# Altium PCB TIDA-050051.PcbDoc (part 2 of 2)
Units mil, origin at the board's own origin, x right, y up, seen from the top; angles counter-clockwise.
Board outline 1055.12 x 796.27 mil, 6 copper layers (Top Layer, Signal Layer 1, Signal Layer 2, Signal Layer 3, Signal Layer 4, Bottom Layer), stack 61 mil thick; 108 components, 65 nets, 370 pads, 157 vias.
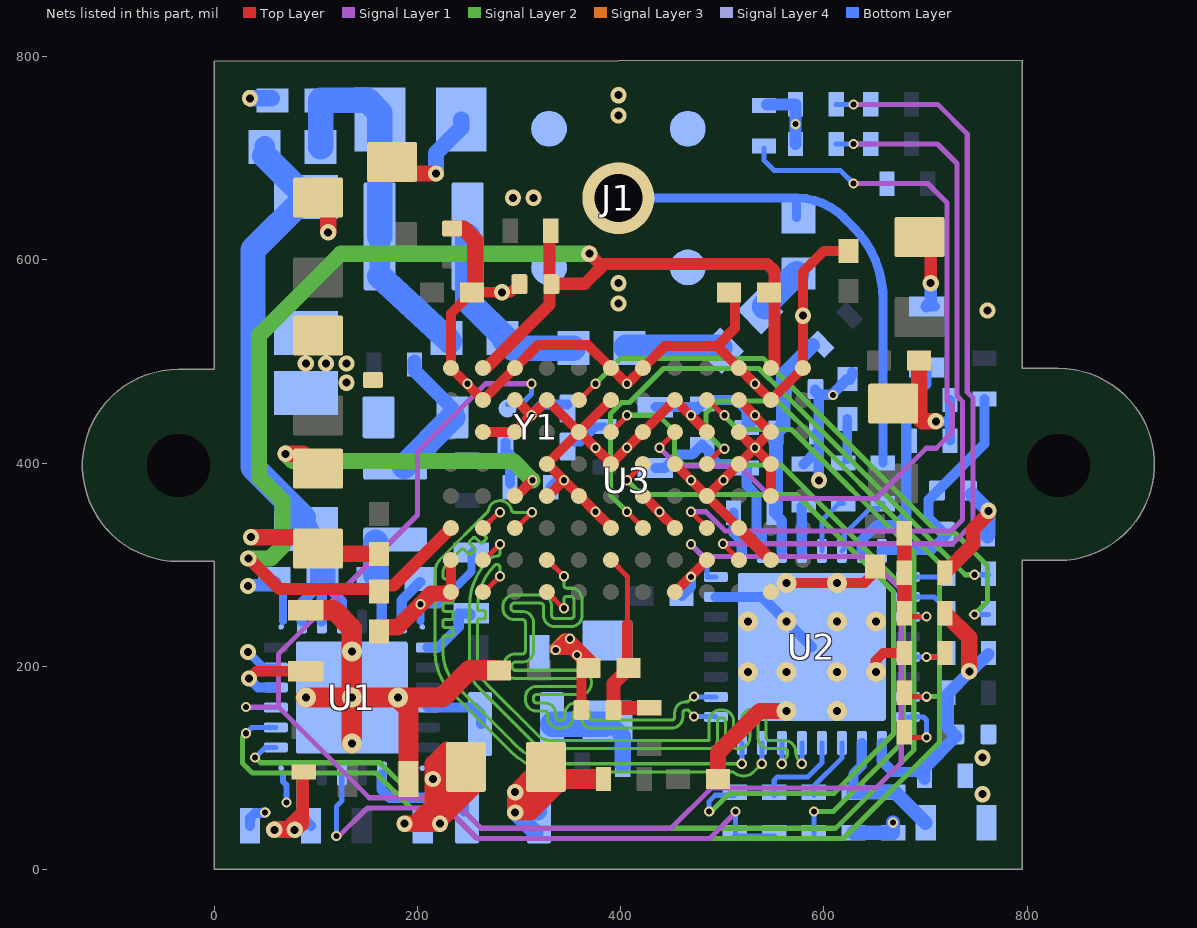
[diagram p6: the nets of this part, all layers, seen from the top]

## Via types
v1: diameter 10, hole 6, Top Layer to Bottom Layer, tented both sides, 79 vias
v2: diameter 16, hole 7.87, Top Layer to Bottom Layer, tented both sides, 61 vias
v3: diameter 19.68, hole 7.87, Top Layer to Bottom Layer, 17 vias

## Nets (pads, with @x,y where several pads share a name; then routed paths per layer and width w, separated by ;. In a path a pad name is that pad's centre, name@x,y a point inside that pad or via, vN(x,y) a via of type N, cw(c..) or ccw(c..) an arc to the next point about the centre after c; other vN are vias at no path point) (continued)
CSI0_D1_N: U2.2 U3.B9 | length 643.2
  Top Layer w3: U3.B9@327.31,304.52 U3.B9@327.97,304.52
  Top Layer w5: U3.B9@327.97,304.52 v1(343.99,288.5)
  Signal Layer 2 w3: 310.75,207.2 cw(c303.04,214.91) 303.04,204 296,204 ccw(c296,201) 293.88,203.12 ccw(c296,201) 293,201 293,199 ccw(c296,199) 293.88,196.88 ccw(c296,199) 296,196 360,196 cw(c360,185.08) 367.72,192.8 367.77,192.76 cw(c360.05,185.03) 370.97,185.03 370.97,183 cw(c359.97,183) 367.75,175.22 ; 310.78,207.22 ccw(c303,215) 314,215 314,243.03 ccw(c303.08,243.03) 310.8,250.76 310.76,250.8 ccw(c303.03,243.08) 303.03,254 295,254 cw(c295,257) 292.88,254.88 cw(c295,257) 292,257 292,259 cw(c295,259) 292.88,261.12 cw(c295,259) 295,262 321,262 cw(c321,259) 323.12,261.12 cw(c321,259) 324,259 324,249.99 ccw(c334.98,249.99) 327.21,242.23 ; 327.22,242.22 ccw(c335,250) 335,239 351.04,239 ccw(c351.04,249.91) 358.75,242.2 ; v1(343.99,288.5) 344,279.75 ccw(c347,279.75) 344.88,277.63 ccw(c347,279.75) 347,276.75 352.28,276.75 cw(c352.28,268.85) 357.87,274.43 357.93,274.38 cw(c348.1,264.55) 362,264.55 362,250 cw(c351,250) 358.78,242.22 ; 348.22,160.78 ccw(c356,153) 345,153 345,150 cw(c342,150) 344.12,147.88 cw(c342,150) 342,147 339,147 cw(c339,150) 336.88,147.88 cw(c339,150) 336,150 336,153.03 ccw(c325.08,153.03) 332.8,160.76 332.76,160.8 ccw(c325.03,153.08) 325.03,164 317,164 cw(c317,167) 314.88,164.88 cw(c317,167) 314,167 314,169 cw(c317,169) 314.88,171.12 cw(c317,169) 317,172 360,172 ccw(c360.01,182.91) 367.72,175.2 ; 348.25,160.8 cw(c355.96,153.09) 355.96,164 358.03,164 cw(c358.03,153.08) 365.76,160.8 365.8,160.76 cw(c358.08,153.03) 369,153.03 369,150 ccw(c372,150) 369.88,147.88 ccw(c372,150) 372,147 450,147 ccw(c450,150) 452.12,147.88 ccw(c450,150) 453,150 453,154 cw(c464,154) 456.22,161.78 ; 456.25,161.8 cw(c463.96,154.09) 463.96,165 466,165 470.74,169.74 cw(c472,168.47) v1(472,170.26)
  Bottom Layer w5: v1(472,170.26) 472.47,169.79 U2.2@493.51,169.79
CSI0_D1_P: U2.1 U3.A9 | length 644.1
  Top Layer w3: v1@343.33,257 v1(343.99,257)
  Top Layer w5: U3.A9@327.31,273.03 v1@343.33,257
  Signal Layer 2 w3: 287.22,249.22 ccw(c295,257) 295,246 303,246 cw(c303,243) 305.12,245.12 cw(c303,243) 306,243 306,215 cw(c303,215) 305.12,212.88 cw(c303,215) 303,212 295.98,212 ccw(c295.98,201.06) 288.24,208.79 288.2,208.75 ccw(c295.92,201.04) 285,201.04 285,198.97 ccw(c295.92,198.97) 288.2,191.24 ; 287.2,249.24 cw(c294.92,256.97) 284,256.97 284,259.04 cw(c294.92,259.04) 287.2,266.75 287.24,266.79 cw(c294.98,259.06) 294.98,270 321.03,270 cw(c321.03,259.08) 328.76,266.8 328.8,266.76 cw(c321.08,259.03) 332,259.03 332,250 ccw(c335,250) 332.88,247.88 ccw(c335,250) 335,247 351,247 ccw(c351,250) 353.12,247.88 ccw(c351,250) 354,250 354,264.51 ccw(c348,264.51) 352.24,268.75 347,268.75 ccw(c347,265.75) 344.88,267.87 ccw(c347,265.75) 344,265.75 v1(343.99,257) ; 288.22,191.22 ccw(c296,199) 296,188 360,188 ; 309.22,159.22 ccw(c317,167) 317,156 325,156 cw(c325,153) 327.12,155.12 cw(c325,153) 328,153 328,149.97 ccw(c338.92,149.97) 331.2,142.24 ; 309.2,159.24 cw(c316.92,166.97) 306,166.97 306,169.04 cw(c316.92,169.04) 309.2,176.75 309.24,176.79 cw(c316.98,169.06) 316.98,180 360,180 ; 331.22,142.22 ccw(c339,150) 339,139 342.02,139 ccw(c342.02,149.94) 349.76,142.2 ; 349.78,142.22 ccw(c342,150) 353,150 353,153 cw(c356,153) 353.88,155.12 cw(c356,153) 356,156 358,156 cw(c358,153) 360.12,155.12 cw(c358,153) 361,153 361,149.97 ccw(c371.92,149.97) 364.2,142.24 ; 359.97,180 ccw(c359.97,183) 362.09,180.88 ccw(c359.97,183) 362.97,183 362.97,185 ccw(c359.97,185) 362.09,187.12 ccw(c359.97,185) 359.97,188 ; 364.22,142.22 ccw(c372,150) 372,139 450.02,139 ccw(c450.02,149.94) 457.76,142.2 ; 457.78,142.22 ccw(c450,150) 461,150 461,154 cw(c464,154) 461.88,156.12 cw(c464,154) 464,157 466,157 472,151 v1(472,150.57)
  Bottom Layer w5: v1(472,150.57) 493.04,150.57 U2.1@493.51,150.1
CSI0_D2_N: U2.32 U3.C11 | length 650.6
  Top Layer w5: U3.C11@264.31,336.02 279.79,351.5 v1(281,351.5)
  Signal Layer 2 w3: v1(281,351.5) 279.74,351.5 264.24,336 262.83,334.59 ccw(c264.24,333.17) 262.83,331.76 267.07,327.51 cw(c265.66,326.1) 267.07,324.69 264.24,321.86 cw(c262.83,323.27) 261.41,321.86 257.17,326.1 ccw(c255.76,324.69) 254.34,326.1 251.51,323.27 ccw(c252.93,321.86) 251.51,320.44 255.76,316.2 cw(c254.34,314.79) 255.76,313.37 252.93,310.54 cw(c251.51,311.96) 250.1,310.54 245.86,314.79 ccw(c244.44,313.37) 243.03,314.79 238.79,310.54 236.12,307.88 228.71,300.47 ccw(c237.72,291.49) 225,291.49 225,288 ccw(c227,288) 227,286 233,286 cw(c233,284) 235,284 235,280 cw(c233,280) 233,278 227,278 ccw(c227,276) 225,276 225,272 ccw(c227,272) 227,270 233,270 cw(c233,268) 235,268 235,264 cw(c233,264) 233,262 227,262 ccw(c227,260) 225,260 225,256 ccw(c227,256) 227,254 233,254 cw(c233,252) 235,252 235,248 cw(c233,248) 233,246 227,246 ccw(c227,244) 225,244 225,240 ccw(c227,240) 227,238 233,238 cw(c233,236) 235,236 235,232 cw(c233,232) 233,230 227,230 ccw(c227,228) 225,228 225,222 225,218 225,214 ccw(c273.28,214) 239.14,179.86 288.47,130.53 297.66,121.34 ccw(c339.53,163.21) 339.53,104 v1(519,104)
  Bottom Layer w5: v1(519,104) 519.1,104.1 U2.32@519.1,124.51
CSI0_D2_P: U2.31 U3.C10 | length 641.4
  Top Layer w3: U3.C10@295.81,336.02 U3.C10@297.02,336.02
  Top Layer w5: U3.C10@297.02,336.02 v1(312.5,351.5)
  Signal Layer 2 w3: 268.85,351.92 268.42,351.5 223.01,306.08 ccw(c237.52,291.57) 217,291.57 217,213.93 ccw(c273.12,213.93) 233.44,174.25 249.04,158.65 282.82,124.87 292,115.69 ; 268.87,351.94 ccw(c266.72,354.04) 269.68,353.51 cw(c281,351.5) 292.25,353.88 ccw(c295.19,354.5) 295.19,351.5 v1(312.5,351.5) ; 292.03,115.66 ccw(c339.49,163.11) 339.49,96 509.53,96 cw(c509.55,93) 511.51,95.28 ccw(c520.73,106.01) 530.04,95.36 v1(538.68,104)
  Bottom Layer w5: v1(538.68,104) 538.79,104.1 U2.31@538.79,124.51
CSI0_D3_N: U2.30 U3.B11 | length 641.2
  Top Layer w3: U3.B11@264.31,304.52 U3.B11@265.52,304.52
  Top Layer w5: U3.B11@265.52,304.52 v1(281,320)
  Signal Layer 2 w3: 260.12,178.91 cw(c282.15,200.93) 251,200.86 cw(c282.15,200.93) 251,200.93 251,258.67 cw(c316.53,258.67) 270.19,305 270.25,305.06 cw(c277.96,297.35) 277.96,308.25 ; 260.6,178.43 312.81,126.22 ccw(c330.24,143.64) 330.17,119 ccw(c330.24,143.64) 330.24,119 487,119 ccw(c487,127) 492.66,121.34 ; 278,308.25 ccw(c278,311.25) 280.12,309.13 ccw(c278,311.25) 281,311.25 v1(281,320) ; 492.68,121.37 ccw(c487.08,126.96) 495,126.96 495,146 cw(c498,146) 495.88,148.12 cw(c498,146) 498,149 500,149 cw(c500,146) 502.12,148.12 cw(c500,146) 503,146 503,129.97 ccw(c513.92,129.97) 506.2,122.24 ; 506.22,122.22 ccw(c514,130) 514,119 516.02,119 ccw(c516.02,129.94) 523.76,122.2 ; 523.78,122.22 ccw(c516,130) 527,130 527,147 cw(c530,147) 527.88,149.12 cw(c530,147) 530,150 532,150 cw(c532,147) 534.12,149.12 cw(c532,147) 535,147 535,129.97 ccw(c545.92,129.97) 538.2,122.24 ; 538.22,122.22 ccw(c546,130) 546,119 561,119 cw(c561.02,116.06) 563.1,118.14 cw(c561.06,116.02) 564,116.02 564,112.91 cw(c547.08,117.5) 559.46,105.09 v1(558.37,104)
  Bottom Layer w5: v1(558.37,104) 558.47,104.1 U2.30@558.47,124.51
CSI0_D3_P: U2.29 U3.A11 | length 641.6
  Top Layer w3: U3.A11@264.31,273.03 U3.A11@265.52,273.03
  Top Layer w5: U3.A11@265.52,273.03 v1(281,288.5)
  Signal Layer 2 w3: 268.12,182.22 318.42,131.92 ccw(c330.31,143.81) 330.31,127 487,127 487,146 cw(c498,146) 490.22,153.78 ; 268.09,182.25 cw(c290.15,204.24) 259,204.24 259,238.69 259,244.62 cw(c261,244.62) 261,246.62 265,246.62 ccw(c265,248.62) 267,248.62 267,252.62 ccw(c265,252.62) 265,254.62 261,254.62 cw(c261,256.62) 259,256.62 259,258.62 cw(c316.63,258.62) 275.88,299.37 cw(c278,297.25) 278,300.25 cw(c278,297.25) 280.12,299.37 cw(c278,297.25) 281,297.25 v1(281,288.5) ; 490.25,153.8 cw(c497.96,146.09) 497.96,157 500.03,157 cw(c500.03,146.08) 507.76,153.8 507.8,153.76 cw(c500.08,146.03) 511,146.03 511,130 ccw(c514,130) 511.88,127.88 ccw(c514,130) 514,127 516,127 ccw(c516,130) 518.12,127.88 ccw(c516,130) 519,130 519,147 cw(c530,147) 522.22,154.78 ; 522.25,154.8 cw(c529.96,147.09) 529.96,158 532.03,158 cw(c532.03,147.08) 539.76,154.8 539.8,154.76 cw(c532.08,147.03) 543,147.03 543,130 ccw(c546,130) 543.88,127.88 ccw(c546,130) 546,127 561.02,127 cw(c561.02,116.06) 568.76,123.79 ; 568.8,123.76 cw(c561.06,116.02) 572,116.02 572.21,115.81 ccw(c586.62,115.81) 576.43,105.62 v1(578.06,104)
  Bottom Layer w5: v1(578.06,104) 578.16,104.1 U2.29@578.16,124.51
DOUTP_F: C21.1 J1.1 L1.1 | length 508.1
  Bottom Layer w8.8: J1.1@397.64,660.72 573.81,660.72 ; L1.1@573,641.56 573,659.91 573.81,660.72 ; C21.1@658,400 658,561.58 ; 658,570 658,561.58 ; 573.81,660.72 cw(c573.81,596.81) 619,642 628.71,632.29 cw(c558,561.58) 646.64,607.86 cw(c558,561.58) 658,561.58
GND: C1.2 C2.2 C3.2 C5.2 C6.2 C7.2 C8.2 C9.1 C10.2 C11.1 C12.2 C13.2 C14.2 C15.2 C16.1 C17.2 C18.1 C19.2 C20.1 C22.2 C24.2 C25.1 C26.2 C27.2 C28.1 C29.2 C31.2 C32.1 C33.2 C34.2 C35.1 C36.2 C37.2 C38.2 C39.2 C40.2 C41.2 C42.1 C43.2 C44.2 C45.1 C46.2 C47.2 C48.2 C49.2 C50.2 C51.2 C52.2 C53.1 C54.2 C55.2 C56.2 J1.2 J1.3 J1.4 J1.5 R8.1 R15.1 R16.1 R20.1 R21.1 R22.1 U1.5 U1.25 U1.A1 U1.A2 U1.A3 U1.A4 U2.7 U2.33@588,219 U3.A2 U3.A5 U3.A12 U3.B2 U3.B4 U3.B12 U3.C3 U3.C5 U3.C7 U3.D2 U3.D4 U3.D6 U3.D8 U3.D9 U3.E2 U3.E3 U3.E5 U3.E7 U3.E9 U3.F2 U3.F3 U3.F4 U3.F6 U3.F8 U3.F10 U3.F11 U3.G2 U3.G3 U3.G5 U3.G7 U3.G9 U3.G10 U3.G11 U3.H1 U3.H3 U3.H6 U3.H7 U3.H10 U3.H12 Y1.2 | length 4672.2
  Top Layer w10: C55.2@90.63,327 C55.2@102,315.63 ; C49.2@102,661.37 C49.2@112,651.37 ; C39.2@162,310.31 C39.2@162,310.79 ; 215,53.62 222,46.62 v2(222,45) ; U3.A12@232.82,273.03 U3.B12@232.82,304.52 ; C12.2@235.63,89 C12.2@247.63,101 ; C41.2@253.69,568 232.82,547.13 U3.H12@232.82,493.5 U3.G11@264.31,462 U3.H10@295.81,493.5 318.31,516 367.8,516 U3.H7@390.3,493.5 390.51,493.5 v1(406.01,478) 406.3,478 U3.H6@421.79,493.5 443.3,515 494.78,515 ; C41.2@256.84,568 v2(283,568) 291.52,568 294.68,571.16 297.38,571.16 300.25,574.03 C42.1@300.25,576 ; U3.F11@264.31,430.51 U3.F10@295.81,430.51 295.81,430.81 v1(312,447) ; U3.G10@295.81,462 297,462 v1(312,447) ; U3.D9@327.31,367.51 328.51,367.51 v1(344,383) ; v1(336,216) 355,216 ; v1@336,217 v1@337,218 ; v1@338,219 v1@346,227 ; 351,220 355,216 ; 352,221 v1@346,227 ; 353,214 v1@354,213 ; C53.1@361.25,157 361.25,190.94 C54.2@368.31,198 C54.2@368.31,198.69 ; C54.2@367.31,199.69 v1@354,213 ; C54.2@374,203 373.66,203.34 v1(350,227) v1@346,227 ; U3.C7@390.3,336.02 390.3,336.7 v1(375,352) 359.49,367.51 U3.D8@358.8,367.51 358.8,368.2 v1(344,383) ; U3.G7@390.3,462 U3.F8@358.8,430.51 ; U3.D6@421.79,367.51 422.49,367.51 v1(438,352) 438,351.31 U3.C5@453.29,336.02 ; U3.A5@453.29,273.03 U3.B4@484.79,304.52 ; U3.E5@453.29,399.01 U3.D4@484.79,367.51 ; U3.F4@484,431.29 U3.G5@453.29,462 U3.F6@421.79,430.51 U3.E7@390.3,399.01 390.3,399.7 v1(375,415) 359.49,430.51 U3.F8@358.8,430.51 ; U3.F4@484.79,430.51 U3.F4@485.49,430.51 ; C44.2@512.31,568 512.31,532.53 494.78,515 ; U3.F3@515.8,430.51 v1@531.79,414.52 ; U3.C3@516.28,336.02 U3.D4@484.79,367.51 ; U3.G3@516.28,462 v1@531.29,447 ; v1@531.57,414.3 U3.E3@516.28,399.01 U3.D4@484.79,367.51 ; v1@531.57,415 547.56,399.01 U3.E2@547.78,399.01 U3.D2@547.78,367.51 ; v1@531.68,445.9 U3.F2@547.07,430.51 ; v1@531.78,415.22 U3.F2@547.07,430.51 ; U3.F2@547.78,430.51 U3.F2@547.07,430.51 ; v3(563.2,281.99) v3(612.8,281.99) 639.68,281.99 C38.2@650,292.31 ; C37.2@624,608.69 599.87,608.69 579.28,588.09 v2(579.28,545) U3.H1@579.28,493.5 U3.G2@547.78,462 532,477.78 v1(532,478) 516.5,493.5 U3.H3@516.28,493.5 494.78,515 ; v3(650.99,194.2) 650.99,205.68 658.32,213 R16.1@679,213 ; v1(312,447) 312.3,447 U3.G9@327.31,462 U3.F8@358.8,430.51 ; v1(344,383) 327.99,399.01 U3.E9@327.31,399.01 U3.F8@358.8,430.51 ; v1@354,213 355,214 355,216
  Top Layer w12: C13.2@90,255 C13.2@97.5,255 ; v2@194,45 214,65 ; v2(215,89) C12.2@243.28,117.28 ; v2(222,45) C12.2@257.36,80.36 ; 223,61.63 C12.2@243,81.63 ; U3.C3@516.28,336.02 U3.B2@547.78,304.52 ; C51.2@694,622.37 705,611.37 v2(705,577)
  Top Layer w14: R15.1@719,292 747,320 747,335 762,350 v2(762,353)
  Top Layer w16: v2(36,327) C55.2@90.63,327 ; C55.2@102,315.63 106.84,310.79 C39.2@162,310.79 ; v2(112,627) C49.2@112,651.37 ; C43.2@162,234.31 166.01,238.32 180.32,238.32 v1(203,261) 213.54,271.54 231.34,271.54 U3.A12@232.82,273.03 ; C40.2@175,696.37 186.37,685 v2(218,685) ; v2(187,45) 194,45 v2(222,45) ; 215,53.62 v2(215,89) ; v2@222,46.62 222,80.38 ; C12.2@228.65,117.65 215,104 v2(215,89) ; C35.1@234,630.75 245.25,630.75 256.84,619.16 256.84,568 C41.2@253.69,568 ; C12.2@235.63,89 v2(215,89) ; C50.2@495.69,89 495.69,114.69 537.01,156.01 v3(563.2,156.01) ; C48.2@693.69,501 693.69,444.31 697,441 v2(710,441)
  Top Layer w20: v3(89.94,169.2) v3(135.21,169.2) ; C13.2@97.5,255 117.79,255 135.21,237.57 v3(135.21,214.47) v3(135.21,169.2) ; v3(135.21,123.92) v3(135.21,169.2) ; C10.2@191,91 191,158.68 v3(180.49,169.2) ; C47.2@280.31,196 251,196 224.2,169.2 v3(180.49,169.2) ; v3(135.21,169.2) v3(180.49,169.2)
  Signal Layer 3 w10: v1@335,216 335,218 344,227 344.5,227 344.5,226.5 355,216 v1(336,216) v1@335,216
  Bottom Layer w6: 67.5,94 67.5,86.52 71,83.02 v1(71,66)
  Bottom Layer w8: v2(33.04,214) 48.32,198.72 U1.5@60.41,198.72 ; C6.2@59.38,283 67.5,274.88 67.5,244.39 ; 202.93,244.39 203,244.46 v1(203,261) 220.91,261 253,293.09 C9.1@253,312
  Bottom Layer w10: C14.2@35,43 35,50.5 40,55.5 47.5,55.5 48,56 v1(50,56) ; C2.2@56.38,759 C2.2@57.38,758 ; v2(215,89) v2@215,89.41 ; v1(312,447) 322.7,457.7 Y1.2@347.51,457.7 ; C56.2@331,376 338,383 v1(344,383) ; C32.1@434,455 C31.2@477,455 ; C52.2@459.69,269 469,278.31 v1(469,288) ; v1(469,447) C31.2@477,455 ; U2.7@493.51,268.21 538.79,268.21 U2.33@588,219 ; v1(532,447) 532,443 C33.2@524,435 524,452 514,462 484,462 C31.2@480,458 C31.2@477,455 ; C28.1@701,554 C28.1@709,554 ; v2(710,441) 724,441 ; C29.2@724,422 724,441 ; C27.2@724,462 724,441
  Bottom Layer w10.3: C34.2@580,399 591.47,410.47 ; C18.1@591.47,470.03 594.35,467.16 601.36,467.16 601.2,467 v1@608.68,467 ; C18.1@591.47,472 C18.1@595,468.47 ; v2(595,383) 595,427.72 C19.2@592.72,430 595,432.27 595,461.3 ; v1(609,467) v1@608.68,467 ; R8.1@623,482.68 608,467.68 v1@608.68,467 ; R8.1@625.14,481.69 627.84,487.53 R8.1@627.84,489.37
  Bottom Layer w12: v2(33,279) 33.77,279.77 56.14,279.77 C6.2@59.38,283 ; R21.1@544,753 R20.1@572,753 v1(572,733.5) R22.1@572,714 ; C28.1@701,554 705,558 v2(705,577)
  Bottom Layer w14: C26.2@629,36 C24.2@665,36 ; C24.2@668,36 v1(668,46) ; C20.1@745.75,369.25 v2(762,353) ; C22.2@761,328 761,329 761.75,329.75 v2@761.75,353
  Bottom Layer w16: v2(35,759) C2.2@56.38,759 ; v2(218,685) 218,705 243,730 C1.2@243,738
  other v1: 357,211 469,383 501,383 406,415 532,415 249,478
  other v2: 756,74 756,110 130,479 89.94,498 109.94,498 129.94,498 761,550 397.64,557 397.64,577 294,661 314,661 397.64,742 397.64,762
  other v3: 612.8,156.01 525.01,194.2 563.2,194.2 612.8,194.2 525.01,243.8 563.2,243.8 612.8,243.8 650.99,243.8
NetC1_1: C1.1 C2.1 L4.1 L5.1 R1.1 | length 364.2
  Bottom Layer w20: L4.1@162.69,583.75 L4.1@162.69,623 ; C1.1@162.69,737.69 C1.1@163,738
  Bottom Layer w25: L5.1@104.56,711 104.56,712 104.62,712.06 C2.1@104.62,757 150.5,757 163,744.5 C1.1@163,738 ; L4.1@162.69,583.75 230.4,520.96 R1.1@231.44,520 ; L4.1@162.69,623 C1.1@162.69,737.69
NetC4_1: C4.1 L6.1 U1.11 | length 74.9
  Bottom Layer w10: C4.1@155.38,283 164.74,273.64 U1.11@164.74,244
  Bottom Layer w25: C4.1@159,290 L6.1@159,322
NetC4_2: C4.2 U1.12 | length 46.5
  Bottom Layer w10: U1.12@184.43,244 184.43,264.8 C4.2@202.62,283
NetC9_2: C9.2 U1.13 | length 64.1
  Bottom Layer w10: U1.13@210.02,218.41 220.25,218.41 231.83,229.99 ; 232.84,231 240.53,238.69 240.53,252 252,252 C9.2@252,250.16
NetC11_2: C11.2 L6.2 R2.1 | length 133.7
  Bottom Layer w14: R2.1@197,491 R2.1@197,500 ; R2.1@200,488 234.42,453.58 C11.2@234.42,445
  Bottom Layer w25: L6.2@187,397 C11.2@234.42,445
NetC12_1: C12.1 L7.2 R3.1 | length 446.2
  Top Layer w12: C12.1@326.37,101 C12.1@338.37,89
  Top Layer w16: 306,75 C12.1@326.37,95.37 ; 307,76 v2(296,76) ; C12.1@315.37,95.37 v2(296,76) ; C12.1@326.37,101 C12.1@326.37,86.37 ; C12.1@334,94 C12.1@326.37,86.37 ; C12.1@339.28,84.28 311,56 v2(296,56) ; v2(296,56) C12.1@326.37,86.37 ; v2(296,56) v2(296,76)
  Top Layer w20: C12.1@338.37,89 R3.1@380,89
  Signal Layer 1 w16: v2(296,56) v2(296,76)
  Signal Layer 3 w16: v2(296,56) v2(296,76)
  Signal Layer 4 w16: v2(296,56) v2(296,76)
  Bottom Layer w16: 300,66 L7.2@322.43,66 ; L7.2@316,36 v2(296,56) ; L7.2@318.43,76 v2(296,76) v2(296,56) ; L7.2@319.43,57 318.43,56 v2(296,56)
NetC13_1: C13.1 U1.4 | length 93
  Top Layer w10: v2(34,188) 41,195 C13.1@94,195
  Bottom Layer w10: v2(34,188) 42.96,179.04 U1.4@60.41,179.04
NetC14_1: C14.1 R5.1 U1.24 | length 254.6
  Top Layer w12: 67,37 87,57 ; v2(79,39) v2@79,40.03 ; 87,46 87,94.5 88,95.5 R5.1@88,96
  Top Layer w16: v2(59,39) v2(79,39) 85,44.97
  Signal Layer 1 w16: v2(59,39) v2(79,39)
  Signal Layer 3 w16: v2(59,39) v2(79,39)
  Signal Layer 4 w16: v2(59,39) v2(79,39)
  Bottom Layer w10: U1.24@86,94.39 86,52 C14.1@95,43
  Bottom Layer w16: v2(59,39) v2(79,39) ; v2@79,40.03 C14.1@87,48.03
NetC15_1: C15.1 L8.2 R4.1 | length 105.9
  Bottom Layer w16: C15.1@383.37,143 C15.1@387,146.63 399,134.63 399,134 402,131 R4.1@402,103
  Bottom Layer w25: L8.2@333,143 C15.1@383.94,143
NetC21_2: C21.2 U2.14 | length 67.9
  Bottom Layer w5: U2.14@617.53,313.49 619.95,315.91 619.95,329.89 645.06,355 653,355 C21.2@658,360
NetC23_1: C23.1 R8.2 | length 45
  Bottom Layer w5: C23.1@619,400 C23.1@623,404
  Bottom Layer w9.5: C23.1@623,404 R8.2@623,443.31
NetC23_2: C23.2 U2.13 | length 57.9
  Bottom Layer w5: U2.13@597.84,313.49 597.84,343.34 614.5,360 C23.2@619,360
NetC30_2: C30.2 U2.9 | length 40.9
  Bottom Layer w10: C30.2@511,351 511,331.22 519.1,323.12 U2.9@519.1,313.49
NetC34_1: C34.1 U2.12 | length 46.3
  Bottom Layer w10: U2.12@578.16,313.49 578.16,357.16 C34.1@580,359
NetC55_1: C55.1 U3.D10 | length 315.4
  Top Layer w10: U3.D10@295.81,367.51 297.51,367.51 v1(313,383)
  Top Layer w16: v2(70,409) 87.37,409 C55.1@102,394.37
  Signal Layer 2 w16: v2(70,409) 77,402 294,402 v1(313,383)
NetC56_1: C56.1 L14.2 Y1.4 | length 86.2
  Bottom Layer w10: L14.2@249,403 Y1.4@288,403 ; Y1.4@286.49,420.3 286.49,408.51 Y1.4@291,404 ; C56.1@291,380 Y1.4@291,409
NetL1_2: L1.2 L2.1 | length 45.8
  Bottom Layer w25: L2.1@541.49,553.51 cw(c544.91,553.51) 542.49,555.93 L1.2@573,586.44
NetL2_2: L2.2 L3.1 | length 92.1
  Bottom Layer w25: L3.1@405.26,513.86 L2.2@497.4,513.86
NetL3_2: L3.2 L4.2 R1.2 | length 190.7
  Bottom Layer w25: L4.2@249.31,623 249.31,559.88 R1.2@289.19,520 ; R1.2@285.56,521 293.56,513 L3.2@353.44,513
NetL7_1: L7.1 U1.20 | length 111.9
  Bottom Layer w10: U1.20@164.33,93.41 164.33,78.67 172.5,70.5 244,70.5 245.57,68.93 L7.1@245.57,57
NetL8_1: L8.1 U1.16 | length 65.3
  Bottom Layer w10: U1.16@210.02,159.35 256.34,159.35 262.57,153.13 L8.1@262.57,143
NetR9_2: R9.2 U2.17 | length 40.4
  Bottom Layer w5: U2.17@682.49,287.9 719.9,287.9 R9.2@722,290
NetR10_2: R10.2 U2.18 | length 48.9
  Bottom Layer w5: U2.18@682.49,268.21 708.6,268.21 722,254.81 R10.2@722,251
NetR11_2: R11.2 U2.27 | length 62.9
  Bottom Layer w5: R11.2@590,73 590,82 617.53,109.53 U2.27@617.53,124.51
NetR12_2: R12.2 U2.28 | length 88.5
  Bottom Layer w5: R12.2@551,73 551,88 554,91 584,91 597.84,104.84 U2.28@597.84,124.51
NetR14_1: R14.1 R16.2 U2.21 | length 60.5
  Top Layer w5: v1(701,209) 715,209 R16.2@719,213
  Bottom Layer w5: U2.21@682.49,209.16 700.84,209.16 v1(701,209) 719,209 R14.1@722,212
NetR23_2: R23.2 U3.E6 | length 720.8
  Top Layer w5: v1(406,383) 421.79,398.79 U3.E6@421.79,399.01
  Signal Layer 2 w5: v1(406,383) 420,369 572.82,369 668.33,273.49 668.33,133.33 609.65,74.65 506.65,74.65 490,58 489,57 v1(487,57)
  Bottom Layer w5: v1(487,57) 487,67 493,73 R23.2@512,73
NetR24_1: R24.1 Y1.3 | length 43
  Bottom Layer w8: Y1.3@347.51,420.3 360.3,420.3 360.9,420.9 369.1,429.1 376,436 R24.1@384,436
nINT: R12.1 R23.1 U1.22 | length 555.4
  Signal Layer 1 w5: v1(120,33) 123,33 150.5,60.5 228.42,60.5 258.42,30.5 487.5,30.5 513,56 v1(513,57)
  Bottom Layer w5: v1(120,33) 120,62 125.37,67.37 U1.22@125.37,94.39 ; v1(513,57) 513,34 512,33 R12.1@551,33
PDB: U1.3 U2.8 Y1.1 | length 1679.3
  Signal Layer 1 w5: v1(31,160) 58,160 62.89,160 ; v1(312,478) 266.85,478 200,411.15 200,348.75 62.89,211.64 62.89,160 ; v1(469,320) 481,308 643.1,308 676,275.1 676,105 651,80 488.92,80 449.42,40.5 262.56,40.5 232.56,70.5 152.39,70.5 62.89,160
  Bottom Layer w5: v1(31,160) 31.65,159.35 U1.3@60.41,159.35 ; Y1.1@288.46,457.7 301.7,457.7 312,468 v1(312,478) ; v1(469,320) 485,304 485,287.9 U2.8@493.51,287.9
SADDR0: R17.1 R20.2 U3.B3 | length 820.6
  Top Layer w5: v1(500.5,320.51) 516.28,304.72 U3.B3@516.28,304.52
  Signal Layer 1 w5: v1(500.5,320.51) 726.65,320.51 746.5,340.36 746.5,464.5 741,470 741,723.9 711.9,753 v1(629,753)
  Bottom Layer w5: R20.2@612,753 v1(629,753) R17.1@646,753
SADDR1: R18.1 R21.2 U3.F5 | length 828.4
  Top Layer w5: v1(438,415) 453.29,430.29 U3.F5@453.29,430.51
  Signal Layer 1 w5: v1(438,415) 456,397 517,397 549,365 651.08,365 700.58,414.5 710.5,414.5 726.5,430.5 726.5,456.22 721,461.72 721,656.12 702.12,675 v1(629,675)
  Bottom Layer w5: R21.2@541,710 541,698 551,688 616,688 v1(629,675) R18.1@662,675
SADDR2: R19.1 R22.2 U3.C4 | length 799.2
  Top Layer w5: v1(469,352.01) 484.79,336.22 U3.C4@484.79,336.02
  Signal Layer 1 w5: v1(469,352.01) 483.75,352.01 502.74,333.01 505.67,333.01 ; 505.69,333 725,333 736.5,344.5 736.5,460.36 731,465.86 731,694.73 711.73,714 v1(629,714)
  Bottom Layer w5: R22.2@612,714 v1(629,714) R19.1@646,714
SCL: R6.1 U1.1 U2.24 U3.G4 | length 1268.3
  Top Layer w5: U3.G4@484.79,462 486,462 501,447 v1(502,447) ; R6.1@679,135 684,130 v1(701,130)
  Signal Layer 2 w5: v1(40,110) 40.43,110 45.43,105 163.06,105 197.56,70.5 232.56,70.5 262.56,40.5 611.5,40.5 688.33,117.33 688.33,130 ; v1(502,447) 502,446 515,433 568,433 688.33,312.67 688.33,130 ; v1(701,130) 688.33,130
  Bottom Layer w5: v1(40,110) 49.98,119.98 U1.1@60.41,119.98 ; U2.24@682.49,150.1 697.9,150.1 701,147 v1(701,130)
SDA: R7.1 U1.2 U2.23 U3.E4 | length 1418
  Top Layer w5: U3.E4@484.79,399.01 484.79,399.21 499.57,414 v1(502,414) ; R7.1@679,174 683,170 v1(701,170)
  Signal Layer 2 w5: v1(31,134) 27.5,130.5 27.5,104.82 37.32,95 158.92,95 193.42,60.5 228.42,60.5 258.42,30.5 619.18,30.5 713.5,124.82 713.5,171 ; v1(502,414) 500,414 484,430 484,449 496.17,461.17 553.83,461.17 572,443 572.14,443 698.33,316.81 698.33,316.67 713.5,301.5 713.5,171 ; v1(701,170) 712.5,170 713.5,171
  Bottom Layer w5: v1(31,134) 36.67,139.67 U1.2@60.41,139.67 ; U2.23@682.49,169.79 700.79,169.79 v1(701,170)
SYS_CHECK: R10.1 U3.G8 | length 574.5
  Top Layer w5: U3.G8@358.8,462 359,462 v1(375,478)
  Signal Layer 2 w5: v1(375,478) 400,503 540.14,503 561.97,481.17 562.11,481.17 580.28,463 580.43,463 712.43,331 729,331 761,299 761,264 v1(748,251) v1@744.54,251
  Bottom Layer w5: v1(748,251) R10.1@762,251
SYS_CLEAR: R9.1 U3.C6 | length 600.4
  Top Layer w5: v1(406.01,352.01) 421.79,336.22 U3.C6@421.79,336.02
  Signal Layer 2 w5: v1(406.01,352.01) 390,368.02 390,448.68 400.82,459.5 408.5,459.5 442,493 536,493 557.83,471.17 557.97,471.17 576.14,453 576.28,453 708.33,320.95 708.33,320.81 723.5,305.64 723.5,305.5 739,290 v1(748,290)
  Bottom Layer w5: v1(748,290) R9.1@762,290
TEMP: R11.1 U3.F7 | length 671.9
  Top Layer w5: U3.F7@390.3,430.51 406,446.21 v1(406,447)
  Signal Layer 2 w5: v1(406,447) 436.8,447 453,430.8 453,407 462.14,397.86 558.14,397.86 678.33,277.67 678.33,126.23 610.11,58 609.11,57 v1(590,57)
  Bottom Layer w5: R11.1@590,33 R11.1@590,36 v1(590,57)
VAA_PIX: C42.2 C43.1 C44.1 L12.2 U3.C12 U3.H2 U3.H11 | length 1363.4
  Top Layer w12: v2(33.43,306) 34,306 36.43,303.57 64,276 159.68,276 C43.1@162,273.68 162,275.65 165.84,279.5 176.3,279.5 U3.C12@232.82,336.02 ; U3.H11@264.31,493.5 265.03,494.22 268.22,494.22 329.87,555.87 C42.2@329.87,574.13 ; L12.2@331.09,628.63 329.87,627.41 C42.2@329.87,574.13 ; v2(369,606) 379.4,595.6 ; U3.H2@547.78,493.5 551.24,496.96 551.24,588.97 544.21,596 384,596 364.5,576.5 332.25,576.5 C42.2@331.75,576 C42.2@329.87,574.13
  Signal Layer 2 w16: v2(33.43,306) 55,306 67,318 67,363 44,386 44,525.74 124.26,606 v2(369,606)
VCC_POC: C3.1 C5.1 C6.1 L5.2 U1.7 U1.8 U1.9 | length 651.5
  Bottom Layer w10: U1.7@86,244 86,262.38 C6.1@105.69,282.06 ; U1.8@105.68,244 C6.1@105.69,282.06 ; U1.9@125.37,244 125.37,264.25 106.62,283 C6.1@105.69,282.06
  Bottom Layer w20: L5.2@49.44,702.49 L5.2@49.44,712 ; C3.1@90,335.07 C3.1@106.62,318.45
  Bottom Layer w25: L5.2@49.44,702.49 C5.1@90,661.93 38,609.93 38,395.85 C3.1@87.5,346.36 ; 71,362.85 71,354.07 C3.1@90,335.07 ; C6.1@106.62,283 C3.1@106.62,318.45
VDD1: C16.2 C17.1 L9.2 R13.2 R14.2 U2.25 | length 289.8
  Top Layer w16: R13.2@720,251 743,228.19 v2(743,195)
  Bottom Layer w10: U2.25@656.9,124.51 656.9,106.84 667.74,96 692,96 C17.1@699,89
  Bottom Layer w12: C17.1@699,89 699,99.75 730.25,131 722,139.25 722,173 743,194 v2(743,195) 745,195 R14.2@762,212
VDD1_CAP: C24.1 C25.2 C26.1 U2.26 | length 135.3
  Bottom Layer w10: C26.1@629,76 629,94 637.21,102.21 U2.26@637.21,124.51
  Bottom Layer w14: C26.1@629,76 C24.1@668,76 670,76 C25.2@700,46
VDD_PLL: C53.2 C54.1 L13.2 U3.B7 | length 197
  Top Layer w5: U3.B7@390.3,304.52 406.42,288.4 406.42,241.42
  Top Layer w10: C53.2@392.75,157 C53.2@394.75,159 ; 406.42,241.42 406.42,199.26 C54.1@407.68,198
  Top Layer w14: C53.2@392.75,157 392.75,183.06 C54.1@407.68,198 ; C53.2@394.75,159 L13.2@428,159
VDDDRV: C20.2 C22.1 L11.2 U2.16 | length 235.5
  Bottom Layer w10: U2.16@656.9,313.49 657.9,314.49 705.49,314.49 C22.1@721,330 718.79,330 703,345.79 703,363.96 758,418.96 L11.2@758,463
VDDDRV_CAP: C27.1 C28.2 C29.1 U2.15 | length 218.1
  Bottom Layer w10: U2.15@637.21,313.49 637.21,324.21 652,339 671,339 681,349 681,458 701,478 C28.2@701,494
VDDPLL: C18.2 C19.1 C30.1 L10.2 U2.11 | length 223.1
  Bottom Layer w10: C30.1@552.72,352.72 C30.1@551,351 558.47,343.53 U2.11@558.47,313.49
  Bottom Layer w14: C30.1@552.72,352.72 C19.1@552.72,430 559.98,437.25 C18.2@560,474 ; C18.2@559.98,472 559.98,486.98 L10.2@588.86,515.86
VDDPLL_CAP: C31.1 C32.2 C33.1 U2.10 | length 198.6
  Bottom Layer w10: C32.2@434,395 443.19,395 456.42,408.22 470.22,408.22 C31.1@480,418 487,411 487,407.79 495.79,399 520,399 C33.1@524,395 524,378 533.5,368.5 533.5,334.86 538.79,329.57 U2.10@538.79,313.49
XCLK: R13.1 R15.2 R25.1 U2.19 | length 116.7
  Top Layer w5: R13.1@682,249 v1(701,249)
  Top Layer w14: R13.1@679,252 R15.2@679,292 R25.1@679,331
  Bottom Layer w5: U2.19@682.49,248.53 700.53,248.53 v1(701,249)
pads on no net: FID1.1 FID2.1 FID3.1 U1.10 U1.19 U2.20 U2.22 U2.33@538.39,169.39 U2.33@538.39,219 U2.33@538.39,268.61 U2.33@588,169.39 U2.33@588,219 U2.33@588,268.61 U2.33@637.61,169.39 U2.33@637.61,219 U2.33@637.61,268.61 U3.B5 U3.D3 U3.D5 U3.E8 U3.F9 U3.G6 U3.H4 U3.H5 U3.H8 U3.H9

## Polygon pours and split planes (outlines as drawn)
GND on Signal Layer 4 "Layer 3 - GND" (solid, remove dead copper, pour order 30): 677.64,-142.36 -132.36,-142.36 -132.36,799.64 917.64,799.64 917.64,-142.36
2V8 on Signal Layer 2 "SIGNAL_LAYER_2_2V8_P028" (solid, remove dead copper, pour order 28): 42.94,338 63.94,317 69,317 69,356 66,359 43.13,359
GND on Signal Layer 1 "Layer 3 - GND" (solid, remove dead copper, pour order 38): 677.64,-142.36 -132.36,-142.36 -132.36,799.64 917.64,799.64 917.64,-142.36
GND on Signal Layer 3 "Layer 3 - GND" (solid, remove dead copper, pour order 40): 677.64,-142.36 -132.36,-142.36 -132.36,799.64 917.64,799.64 917.64,-142.36

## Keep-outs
Signal Layer 1:
  lines w11: 472,150.57 472,249 ; 519,104 578.06,104
Signal Layer 3:
  lines w11: 472,150.57 472,249 ; 519,104 578.06,104
Signal Layer 4:
  lines w11: 472,150.57 472,249 ; 519,104 578.06,104
Keep-Out Layer:
  text ".Layer_Name" at 577,-858.49 h60

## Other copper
Top Layer:
  region net GND: 77,546 77,492 97,472 166,472 166,490 151,490 127,514 127,546
  region net GND: 125.47,211 226,211 233,204 242,204 245.26,207.26 292,207.26 292,186 253,147 231.74,147 201,116.26 201,73.08 181,73.08 181,86.72 153.72,114 127.21,114 106,135.21 106,148.92 94.92,160 87,160 81,166 81,173 86,178 111,178 125.47,192.47
  region net GND: 510,137 518,129 650,129 666,145 666,257 660,263 660,310 640.54,310 621.54,291 553,291 533,271 517,255 510,248
  text ".Layer_Name" at 577,-858.49 h60
Signal Layer 4:
  pour cut-out: 556,656 590,656 590,626 556,626
  pour cut-out: 607,408 631,408 631,392 607,392
  pour cut-out: 646,408 670,408 670,392 646,392
  pour cut-out: 646,368 670,368 670,352 646,352
  pour cut-out: 607,368 631,368 631,352 607,352
Bottom Layer:
  region net 3V3: 150.5,484.39 146,488.89 146,526.45 150.44,530.89 178.44,530.89 184,525.33 184,492.67 175.91,484.58
  region net GND: 199,106 199,81 220,81 223,84 223,106
  region net GND: 289.37,670.56 289.37,650.88 321.5,650.88 321.5,670.56
  region net GND: 387.8,584.58 407.48,584.58 407.48,552.45 387.8,552.45
  region net GND: 387.8,768.99 407.48,768.99 407.48,736.86 387.8,736.86
  region net GND: 224.5,60.5 230,55 230,32 223,25 185,25 179,31 179,55.25 184.73,60.5
  region net GND: 310,231 330,231 344,245 412,245 412,205 361.57,205 351.57,195 310,195
  region net GND: 59,550 59,447 130,447 153,424 178,424 178,466 157,466 140,483 140,503 122,521 122,550
  region net GND: 769.92,28 747.92,28 730.92,45 730.92,105 753.92,128 753.92,141 755.92,143 767.08,143 770.08,140
  text ".Layer_Name" at 577,-858.49 h60

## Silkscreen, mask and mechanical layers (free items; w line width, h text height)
Top Overlay:
  lines w10: -217.99,62.26 -197.99,2.26 ; -217.99,729.67 -197.99,789.67 ; -207.99,2.26 -187.99,2.26 ; -207.99,789.67 -187.99,789.67 ; -197.99,110.05 -197.99,2.26 ; -197.99,681.88 -197.99,789.67 ; -177.99,62.26 -197.99,2.26 ; -177.99,729.67 -197.99,789.67 ; 2.33,-111 2.33,-91 ; 61.63,731.63 62.99,330.99 ; 62.33,-121 2.33,-101 ; 62.33,-81 2.33,-101 ; 62.63,731.63 732.63,731.63 732.63,61.63 62.63,61.63 62.99,232.99 ; 110.12,-101 2.33,-101 ; 681.95,-101 789.74,-101 ; 729.74,-121 789.74,-101 ; 729.74,-81 789.74,-101 ; 789.74,-111 789.74,-91
  text "787.402mil" at -162,120.05 h60 r90
  text "787.402mil" at 120.12,-136.99 h60
  text ".Layer_Name" at 577,-858.49 h60
Bottom Overlay:
  lines w3: 47,687 49.39,689.39 54,689.39 168.73,689.39 176,696.66 ; 498.71,23.29 504,18 677,18 682.29,23.29 ; 771.71,101.29 777,96 ; 772,19 777.29,24.29 777.29,394.29 ; 772,115.71 777.29,121 ; 772,516.29 777.29,511 777.29,458.71
  text ".Layer_Name" at 577,-858.49 h60
Top Paste:
  text ".Layer_Name" at 577,-858.49 h60
Bottom Paste:
  text ".Layer_Name" at 577,-858.49 h60
Top Solder:
  text ".Layer_Name" at 577,-858.49 h60
  text ".Layer_Name" at 577,-858.49 h60
Bottom Solder:
  text ".Layer_Name" at 577,-858.49 h60
Drill Guide:
  text ".Layer_Name" at 577,-858.49 h60
M1 Board Outline:
  lines w10: 795.28,0 0,0 0,303.15 -35.43,303.15 cw(c-35.43,397.64) -35.43,492.13 0,492.13 0,795.28 795.28,796.27 795.28,493.11 830.71,493.11 cw(c830.71,398.62) 830.71,304.14 795.3,304.14 795.28,0.99
  text ".Layer_Name" at 577,-858.49 h60
M2 Board Dimensions:
  rectangle: 0,-275 125,-150
  rectangle: 125,-400 500,-275
  lines w7: 0,-275 1000,-275 ; 125,-400 125,-150 ; 250,-400 250,-150 ; 500,-400 500,-150 ; 750,-400 750,-150 ; 0,-400 1000,-400 1000,-150 0,-150 0,-400
  text ".Layer_Name" at 577,-858.49 h60
M3 3D STEP Top:
  text ".Layer_Name" at 577,-858.49 h60
M4 3D STEP Bottom:
  text ".Layer_Name" at 577,-858.49 h60
M5 Assembly Top:
  lines w10: -292,-930.17 6308,-930.17 ; -292,-726.83 6310,-726.83 ; -292,-523.5 -292,-1133.5 3713,-1133.5 6310,-1133.5 6310,-523.5 -291.5,-523.5 -291.5,-1133.5 1284,-1133.5 ; 2173,-1133.5 2173,-523.5 ; 3440,-726.83 3440,-523.5 ; 4280,-726.83 4280,-523.5 ; 4902,-1140 4902,-937.17
  text "COMPONENTS MARKED 'DNP' SHOULD NOT BE POPULATED." at 1153.5,-318.5 h60
  text "ASSEMBLY VARIANT:" at 1153,-434 h60
  text ".VariantName" at 2189,-434 h60
  text "PCB VIEWED FROM TOP SIDE" at -228.5,-655.67 h60
  text "BOARD #:" at 2248,-655.67 h60
  text ".PRJ_Number" at 2793.5,-655.67 h60
  text "REV:" at 3638,-655.67 h60
  text ".PCB_Rev" at 3929.5,-655.67 h60
  text "SVN REV:" at 4476,-655.67 h60
  text ".VersionControl_RevNumber" at 4982,-655.67 h60
  text "TID #:" at 2248,-859 h60
  text ".TID" at 2793.5,-859 h60
  text "PLOT NAME =" at -228.5,-1064.34 h60
  text ".plot_File_Name" at 577,-1064.34 h60
  text "GENERATED    :" at 2250,-1064.34 h60
  text ".Print_Date" at 3119.5,-1064.34 h60
  text ".Print_Time" at 3848.5,-1064.34 h60
  text "TEXAS INSTRUMENTS" at 5113,-1064.34 h60
M6 Assembly Bottom:
  lines w10: -292.5,-727.33 6309.5,-727.33 ; -290.5,-930.67 6309.5,-930.67 ; 1115.5,-1140.5 1115.5,-937.67 ; 1737.5,-727.33 1737.5,-524 ; 2577.5,-727.33 2577.5,-524 ; 3844.5,-1134 3844.5,-524 ; 4733.5,-1134 6309,-1134 6309,-524 -292.5,-524 -292.5,-1134 2304.5,-1134 6309.5,-1134 6309.5,-524
  text "COMPONENTS MARKED 'DNP' SHOULD NOT BE POPULATED." at 6102,-318 h60
  text ".VariantName" at 5058,-434 h60
  text "ASSEMBLY VARIANT:" at 6097,-434 h60
  text ".VersionControl_RevNumber" at 1035.5,-656.17 h60
  text "SVN REV:" at 1541.5,-656.17 h60
  text ".PCB_Rev" at 2088,-656.17 h60
  text "REV:" at 2379.5,-656.17 h60
  text ".PRJ_Number" at 3224,-656.17 h60
  text "BOARD #:" at 3769.5,-656.17 h60
  text "PCB VIEWED FROM BOTTOM SIDE" at 6246,-656.17 h60
  text ".TID" at 3224,-859.5 h60
  text "TID #:" at 3769.5,-859.5 h60
  text "TEXAS INSTRUMENTS" at 904.5,-1064.84 h60
  text ".Print_Time" at 2169,-1064.84 h60
  text ".Print_Date" at 2898,-1064.84 h60
  text "GENERATED    :" at 3767.5,-1064.84 h60
  text ".plot_File_Name" at 5440.5,-1064.84 h60
  text "PLOT NAME =" at 6246,-1064.84 h60
M9 Title Sheet:
  drawing of 57 lines, arcs and shapes, not listed
  text "1" at 739.84,8036.5 h70
  text "2" at 3235.5,8036.5 h70
  text "3" at 5724.84,8036.5 h70
  text "4" at 8231.51,8036.5 h70
  text "5" at 10730.5,8036.5 h70
  text "6" at 13235.5,8036.5 h70
  text "A" at -416.5,6893.5 h70
  text "A" at 14383.5,6893.5 h70
  text "B" at -416.5,4513.5 h70
  text "B" at 14383.5,4513.5 h70
  text "C" at -416.5,2138.5 h70
  text "C" at 14383.5,2138.5 h70
  text "PROJECT TITLE:" at 11343.5,277.5 h45
  text ".PRJ_Title" at 11393.5,144.17 h70
  text "DESIGNED FOR:" at 11343.5,-23.5 h45
  text ".PRJ_Customer" at 11393.5,-163.5 h70
  text "D" at -416.5,-231.5 h70
  text "D" at 14383.5,-231.5 h70
  text "FILE NAME:" at 11343.5,-323.5 h45
  text ".PCB_File_Name_No_Path" at 11393.5,-443.5 h70
  text "Texas Instruments (TI) and/or its licensors do not warrant the accuracy or completeness of this specification" at 6374,-605.34 h45
  text "ENGINEER:" at 11343.5,-613.5 h45
  text "LAYOUT BY:" at 12848.5,-613.5 h45
  text "or any information contained therein. TI and/or its licensors do not warrant that this design will meet" at 6329.01,-718 h45
  text ".PRJ_Engineer" at 11393.5,-768.49 h70
  text ".PCB_Layout" at 12899,-768.49 h70
  text "the specifications, will be suitable for your application or fit for any particular purpose, or will operate in" at 6329.01,-830.67 h45
  text ".Layer_Name" at 577,-858.49 h60
  text "ALTIUM DESIGNER VERSION:" at 12848.5,-923.5 h45
  text "an implementation. TI and/or its licensors do not warrant that the design is production worthy. You should" at 6329.01,-943.33 h45
  text "completely validate and test your design implementation to confirm the system functionality for your application." at 6374,-1056 h45
  text ".print_Scale" at 11393.5,-1056.83 h70
  text ".Application_BuildNumber" at 12899,-1056.83 h70
  text "1" at 739.84,-1263.5 h70
  text "2" at 3235.5,-1263.5 h70
  text "3" at 5724.84,-1263.5 h70
  text "4" at 8231.51,-1263.5 h70
  text "5" at 10730.5,-1263.5 h70
  text "6" at 13235.5,-1263.5 h70
M10 Fab Notes:
  drawing of 189 lines, arcs and shapes, not listed
  text "DESIGN INFORMATION" at 12382.02,6356.17 h60
  text "MIN. TRACK WIDTH:" at 11737.46,6224.05 h60
  text "8" at 12833.7,6224.05 h60
  text "MIL" at 12988.46,6224.05 h60
  text "MIN. CLEARANCE:" at 11737.46,6099.92 h60
  text "0.2" at 12773.7,6099.93 h60
  text "mm" at 12988.46,6099.92 h60
  text "MIN. VIA PAD SIZE:" at 11737.46,5975.8 h60
  text "24" at 12803.71,5975.8 h60
  text "MIL" at 12988.46,5975.8 h60
  text "0.05mm (2MIL)" at 12432.46,5845.9 h60
  text "MINIMUM ANNULAR RING" at 11408.23,5837.67 h60
  text "EXTERNAL" at 13140.46,5837.67 h60
  text "PER" at 11608.23,5727.55 h60
  text "IPC-D-275 CLASS 2 LEVEL C" at 11828.23,5727.54 h60
  text "MIL, HOLES" at 13316.46,5627.07 h60
  text "+/-" at 12924,5618.48 h60
  text "+/-" at 13778,5618.48 h60
  text "REGISTRATION TOLERANCES:" at 11408.23,5617.42 h60
  text "METAL" at 12608,5617.42 h60
  text "5" at 13184.2,5617.42 h60
  text "3" at 14017.2,5617.42 h60
  text "MIL" at 14133.46,5617.42 h60
  text "HOLE SIZE TOLERANCE (UNLESS OTHERWISE SPECIFIED):" at 11408.23,5519.1 h60
  text "+/-" at 13778,5516.23 h60
  text "3" at 14017.2,5515.17 h60
  text "MIL" at 14133.46,5515.17 h60
  text "MATERIAL:" at 11333.46,5377.52 h60
  text "FR-4 High Tg" at 12319.9,5249 h60
  text "X" at 12175.46,5241.01 h60
  text "FR-408" at 11754.46,5236.49 h60
  text "OTHER" at 13242.46,5236.49 h60
  text "62 MIL (1.6mm) +/-10%" at 12074.56,5093.46 h60
  text "X" at 11954.46,5091.01 h60
  text "THICKNESS:" at 11408.23,5085.24 h60
  text "OTHER" at 13359.46,5085.24 h60
  text "TOLERANCE:" at 11408.23,4946.92 h60
  text "X" at 12256.46,4946.92 h60
  text "ANSI IPC-6012 TYPE 3 CLASS 2" at 12434.48,4946.92 h60
  text "OTHER +/-" at 12434.46,4802.73 h60
  text "BOW & TWIST:" at 11408.23,4657.54 h60
  text "X" at 12256.46,4657.54 h60
  text "ANSI IPC-6012 TYPE 3 CLASS 2" at 12434.48,4657.54 h60
  text "OTHER +/-" at 12434.46,4510.85 h60
  text "DRILLING:" at 11333.46,4380.23 h60
  text "NC_DRILL FILES" at 13094.46,4275.04 h60
  text "REFERENCE:" at 11408.23,4271.1 h60
  text "X" at 12065.46,4271.01 h60
  text "AS SHOWN" at 12243.46,4271.1 h60
  text "X" at 12966.46,4271.1 h60
  text "OTHER" at 13392.46,4128.85 h60
  text "PTH COPPER THICKNESS:" at 11407.91,4125.32 h60
  text "X" at 12547.14,4125.32 h60
  text "20-30 um" at 12675.14,4125.32 h60
  text "BOARD FINISH:" at 11333.46,3977.73 h60
  text "SILKSCREEN:" at 11488.68,3867.6 h60
  text "X" at 12446.46,3867.6 h60
  text "TOP" at 12563.46,3867.6 h60
  text "X" at 12956.46,3867.6 h60
  text "BOTTOM" at 13074.46,3867.6 h60
  text "SILKSCREEN COLOR:" at 11488.68,3712.41 h60
  text "X" at 12445.46,3712.41 h60
  text "WHITE" at 12563.46,3712.41 h60
  text "OTHER" at 13074.46,3712.41 h60
  text "X" at 12576.46,3568.96 h60
  text "GREEN" at 12694.46,3568.96 h60
  text "OTHER" at 13312.46,3568.96 h60
  text "SOLDER RESIST COLOR:" at 11488.68,3562.1 h60
  text "X" at 12576.46,3414.71 h60
  text "MATTE" at 12694.46,3414.71 h60
  text "SEMI-GLOSS" at 13312,3414.07 h60
  text "IMMERSION GOLD (ENIG)" at 12394.46,3241.94 h60
  text "ENEPIG" at 13732,3234.72 h60
  text "SURFACE FINISH:" at 11333.46,3233.72 h60
  text "X" at 12216.46,3233.72 h60
  text "IMM. TIN/SILVER OR EQUIV" at 11663,3096.4 h60
  text "OTHER" at 13094.46,3092.47 h60
  text "ARRAY/PANEL:" at 11333.46,2937.09 h60
  text "CUT AND TRIM PER M1 BOARD OUTLINE" at 12394.46,2928.87 h60
  text "N.C. ROUTE" at 12394.46,2792.9 h60
  text "X" at 13082.46,2792.9 h60
  text "V. SCORE" at 13260.46,2792.9 h60
  text "CERTIFICATION:" at 11333.46,2663.77 h60
  text "MATERIALS AND WORKMANSHIP FOR ALL PCBS" at 12058.46,2663.77 h60
  text "TO MEET OR EXCEED THE REQUIREMENTS OF:" at 12058.46,2569.71 h60
  text "X" at 11695.97,2441.08 h60
  text "ANSI IPC-A-600F CLASS ->" at 11823.96,2441.08 h60
  text "X" at 13471.97,2441.08 h60
  text "2" at 13581.96,2441.08 h60
  text "1" at 13266.96,2439.58 h60
  text "3" at 13935.96,2439.58 h60
  text "X" at 12507.97,2293.39 h60
  text "RoHS" at 12635.96,2293.39 h60
  text "OTHER" at 13280.36,2293.39 h60
  text "PER ORDER" at 13677.42,2293.39 h60
  text "ALL BOARDS MUST MEET OR EXCEED UL94-V0 REQUIREMENTS." at 11361,2139.57 h60
  text "PCB MUST BEAR THE UL94V-0 UL REGISTERED MATERIAL ID NUMBER" at 11361,2023.5 h60
  text "ADDITIONAL REQUIREMENTS:" at 11333.46,1854.08 h60
  text "MICROSECTION:" at 11408.23,1746.95 h60
  text "YES" at 12313.96,1746.95 h60
  text "REQUIRED" at 13175.46,1602.62 h60
  text "BARE BOARD ELEC. TEST:" at 11408.23,1599.76 h60
  text "NONE" at 12713.96,1599.76 h60
  text "X" at 13057.46,1599.76 h60
  text "PER ORDER" at 13767.46,1599.76 h60
  text "XX MIL VIAS REQUIRE NON-CONDUCTIVE FILL AND PLANARIZE" at 11576.38,1394.82 h59
  text "XX MIL VIAS REQUIRE CONDUCTIVE FILL AND PLANARIZE" at 11584.38,1290.84 h60
  text "OUTER XX MIL TRACES REQUIRE 50 OHM SINGLE-ENDED IMPEDANCE" at 11583.39,1127.46 h58
  text "LAYER 2 & 3 (INNER LAYERS) XX MIL WIDE, XX MIL SPACE / TRACES REQUIRE 100 OHM DIFFERENTIAL IMPEDANCE" at 11575.39,891.74 h60
  text ".Layer_Name" at 577,-858.49 h60
M11 Gerber Information:
  lines w10: -292,-930.17 6308,-930.17 ; -292,-726.83 6310,-726.83 ; -292,-523.5 -292,-1133.5 3713,-1133.5 6310,-1133.5 6310,-523.5 -291.5,-523.5 -291.5,-1133.5 1284,-1133.5 ; 2173,-1133.5 2173,-523.5 ; 3440,-726.83 3440,-523.5 ; 4280,-726.83 4280,-523.5 ; 4902,-1140 4902,-937.17
  text "ALL ARTWORK VIEWED FROM TOP SIDE" at -228.5,-655.67 h60
  text "BOARD #:" at 2248,-655.67 h60
  text ".PRJ_Number" at 2793.5,-655.67 h60
  text "REV:" at 3638,-655.67 h60
  text ".PCB_Rev" at 3929.5,-655.67 h60
  text "SVN REV:" at 4476,-655.67 h60
  text ".VersionControl_RevNumber" at 4982,-655.67 h60
  text "LAYER NAME =" at -228.5,-858.49 h60
  text "TID #:" at 2248,-859 h60
  text ".TID" at 2793.5,-859 h60
  text "PLOT NAME =" at -228.5,-1064.34 h60
  text ".plot_File_Name" at 577,-1064.34 h60
  text "GENERATED    :" at 2250,-1064.34 h60
  text ".Print_Date" at 3119.5,-1064.34 h60
  text ".Print_Time" at 3848.5,-1064.34 h60
  text "TEXAS INSTRUMENTS" at 5113,-1064.34 h60
M12 Stackup:
  drawing of 399 lines, arcs and shapes, not listed
  text "Layer" at 6446.09,6699 h60
  text "Name" at 6856,6699 h60
  text "Material" at 7795.74,6699 h60
  text "Thickness" at 8655.51,6699 h60
  text "Constant" at 9305.34,6699 h60
  text "Board Layer Stack" at 9875.2,6699 h60
  text "1" at 6446.09,6579 h60
  text "Top Overlay" at 6856,6579 h60
  text "2" at 6446.09,6459 h60
  text "Top Solder" at 6856,6459 h60
  text "Solder Resist" at 7795.74,6459 h60
  text "0.50mil" at 8655.51,6459 h60
  text "3.5" at 9305.34,6459 h60
  text "3" at 6446.09,6339 h60
  text "Top Layer" at 6856,6339 h60
  text "Copper" at 7795.74,6339 h60
  text "1.40mil" at 8655.51,6339 h60
  text "4" at 6446.09,6219 h60
  text "Dielectric 1" at 6856,6219 h60
  text "FR-4 High Tg" at 7795.74,6219 h60
  text "5.10mil" at 8655.51,6219 h60
  text "4.2" at 9305.34,6219 h60
  text "5" at 6446.09,6099 h60
  text "Signal Layer 1" at 6856,6099 h60
  text "Copper" at 7795.74,6099 h60
  text "1.40mil" at 8655.51,6099 h60
  text "6" at 6446.09,5979 h60
  text "Dielectric 2" at 6856,5979 h60
  text "FR-4 High Tg" at 7795.74,5979 h60
  text "8.00mil" at 8655.51,5979 h60
  text "4.2" at 9305.34,5979 h60
  text "7" at 6446.09,5859 h60
  text "Signal Layer 2" at 6856,5859 h60
  text "Copper" at 7795.74,5859 h60
  text "1.40mil" at 8655.51,5859 h60
  text "8" at 6446.09,5739 h60
  text "Dielectric 4" at 6856,5739 h60
  text "FR-4 High Tg" at 7795.74,5739 h60
  text "26.40mil" at 8655.51,5739 h60
  text "4.2" at 9305.34,5739 h60
  text "9" at 6446.09,5619 h60
  text "Signal Layer 3" at 6856,5619 h60
  text "Copper" at 7795.74,5619 h60
  text "1.40mil" at 8655.51,5619 h60
  text "10" at 6446.09,5499 h60
  text "Dielectric 5" at 6856,5499 h60
  text "FR-4 High Tg" at 7795.74,5499 h60
  text "8.00mil" at 8655.51,5499 h60
  text "4.2" at 9305.34,5499 h60
  text "11" at 6446.09,5379 h60
  text "Signal Layer 4" at 6856,5379 h60
  text "Copper" at 7795.74,5379 h60
  text "1.40mil" at 8655.51,5379 h60
  text "12" at 6446.09,5259 h60
  text "Dielectric 3" at 6856,5259 h60
  text "FR-4 High Tg" at 7795.74,5259 h60
  text "5.10mil" at 8655.51,5259 h60
  text "4.2" at 9305.34,5259 h60
  text "13" at 6446.09,5139 h60
  text "Bottom Layer" at 6856,5139 h60
  text "Copper" at 7795.74,5139 h60
  text "1.40mil" at 8655.51,5139 h60
  text "14" at 6446.09,5019 h60
  text "Bottom Solder" at 6856,5019 h60
  text "Solder Resist" at 7795.74,5019 h60
  text "0.50mil" at 8655.51,5019 h60
  text "3.5" at 9305.34,5019 h60
  text "15" at 6446.09,4899 h60
  text "Bottom Overlay" at 6856,4899 h60
  text ".Layer_Name" at 577,-858.49 h60
M13 Component Bodies Top:
  text ".Layer_Name" at 577,-858.49 h60
M14 Component Bodies Bottom:
  text ".Layer_Name" at 577,-858.49 h60
M15 Courtyards Top:
  text ".Layer_Name" at 577,-858.49 h60
M16 Courtyards Bottom:
  text ".Layer_Name" at 577,-858.49 h60
Drill Drawing:
  circle w10: c5363.72,3387.96 r27.63
  lines w10: 5336.09,2987.38 5391.34,2987.38 5391.34,3042.63 5336.09,3042.63 5336.09,2987.38 ; 5336.09,3166.95 5391.34,3166.95 5363.72,3111.7 5336.09,3166.95 ; 5336.09,3249.83 5349.9,3249.83 5363.72,3236.02 5377.53,3249.83 5391.34,3249.83 5377.53,3263.64 5391.34,3277.46 5377.53,3277.46 5363.72,3291.27 5349.9,3277.46 5336.09,3277.46 5349.9,3263.64 5336.09,3249.83 ; 5336.09,3484.66 5363.72,3498.47 5391.34,3484.66 5377.53,3512.28 5391.34,3539.91 5363.72,3526.1 5336.09,3539.91 5349.9,3512.28 5336.09,3484.66
  lines w12: 5286,2950.08 8517.49,2950.08 ; 5286,3571.68 8517.49,3571.68 ; 5623.86,2825.76 5623.86,3696 ; 5955.86,2825.76 5955.86,3696 ; 6592.43,2825.76 6592.43,3696 ; 6851.57,2825.76 6851.57,3696 ; 7226.72,2825.76 7226.72,3696 ; 7951.05,2825.76 7951.05,3696 ; 5286,2825.76 8517.49,2825.76 8517.49,3696 5286,3696 5286,2825.76
  text "Symbol" at 5360.59,3608.98 h72
  text "Quantity" at 5661.16,3608.98 h72
  text "Finished Hole Size" at 5993.16,3608.98 h72
  text "Plated" at 6629.72,3608.98 h72
  text "Hole Type" at 6888.86,3608.98 h72
  text "Drill Layer Pair" at 7264.02,3608.98 h72
  text "Hole Tolerance" at 7988.35,3608.98 h72
  text "2" at 5661.16,3484.66 h60
  text "62.99mil (1.600mm)" at 5993.16,3484.66 h60
  text "NPTH" at 6629.72,3484.66 h60
  text "Round" at 6888.86,3484.66 h60
  text "Top Layer - Bottom Layer" at 7264.02,3484.66 h60
  text "79" at 5661.16,3360.34 h60
  text "6.00mil (0.152mm)" at 5993.16,3360.34 h60
  text "PTH" at 6629.72,3360.34 h60
  text "Round" at 6888.86,3360.34 h60
  text "Top Layer - Bottom Layer" at 7264.02,3360.34 h60
  text "61" at 5661.16,3236.02 h60
  text "7.87mil (0.200mm)" at 5993.16,3236.02 h60
  text "PTH" at 6629.72,3236.02 h60
  text "Round" at 6888.86,3236.02 h60
  text "Top Layer - Bottom Layer" at 7264.02,3236.02 h60
  text "17" at 5661.16,3111.7 h60
  text "7.87mil (0.200mm)" at 5993.16,3111.7 h60
  text "PTH" at 6629.72,3111.7 h60
  text "Round" at 6888.86,3111.7 h60
  text "Top Layer - Bottom Layer" at 7264.02,3111.7 h60
  text "1" at 5661.16,2987.38 h60
  text "47.24mil (1.200mm)" at 5993.16,2987.38 h60
  text "PTH" at 6629.72,2987.38 h60
  text "Round" at 6888.86,2987.38 h60
  text "Top Layer - Bottom Layer" at 7264.02,2987.38 h60
  text "160 Total" at 5661.16,2863.06 h60
  text ".Layer_Name" at 577,-858.49 h60
Mechanical 17:
  text ".Layer_Name" at 577,-858.49 h60
Mechanical 18:
  text ".Layer_Name" at 577,-858.49 h60
Mechanical 19:
  text ".Layer_Name" at 577,-858.49 h60

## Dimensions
0,-400 to 1000,-400 on M2 Board Dimensions
0,0 to -87,788 on M2 Board Dimensions
0,0 to 0,303.15 on M2 Board Dimensions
